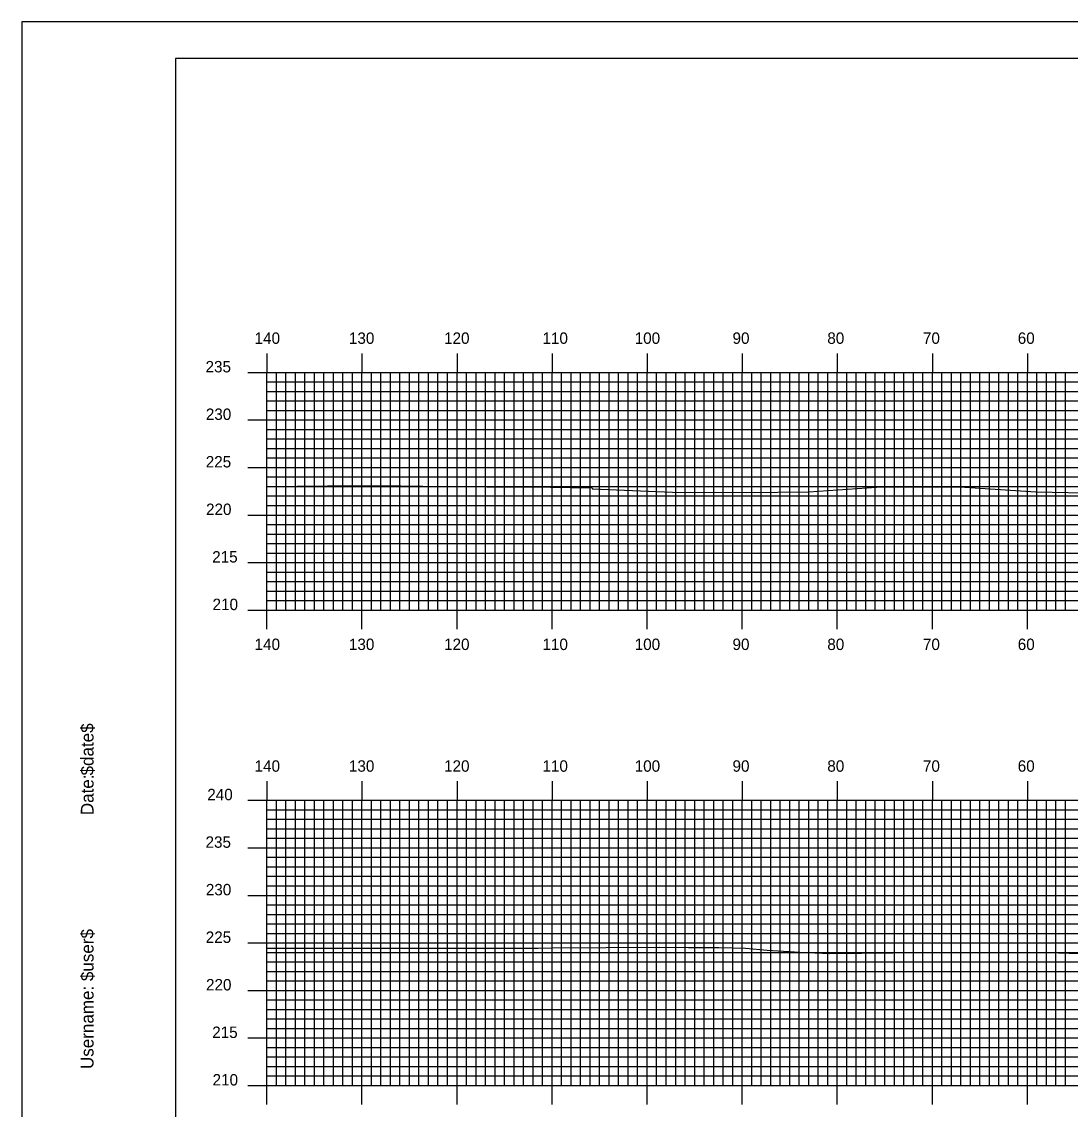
# Model space of a CAD drawing. Extents: x 1803897 to 1804240, y 442591 to 442811.
# Drawn here: x 1803896.9 to 1804007.2, y 442696.2 to 442810.5 of the extents above; entities that cross this region are included whole.
import ezdxf

# ---------------------------------------------------------------- set-up
doc = ezdxf.new("R2010")
doc.units = 0
for name, color, linetype in [('BORDER', 7, 'Continuous'), ('H_V ANNOTATION', 7, 'Continuous'), ('MAJOR', 7, 'Continuous'), ('MINOR', 7, 'Continuous'), ('PLOT BOUNDARY', 7, 'Continuous'), ('S_Roadway_Centerline', 7, 'Continuous')]:
    doc.layers.add(name, color=color, linetype=linetype)

msp = doc.modelspace()

# ---------------------------------------------------------------- linework, layer by layer
at = {"layer": 'BORDER'}
msp.add_lwpolyline([(1803913.05, 442596.67), (1804233.05, 442596.67), (1804233.05, 442806.67), (1803913.05, 442806.67)], close=True, dxfattribs=at)
at = {"layer": 'MAJOR'}
for p, q in [((1803922.65, 442775.67), (1803922.65, 442773.67)), ((1803932.65, 442775.67), (1803932.65, 442773.67)), ((1803942.65, 442775.67), (1803942.65, 442773.67)), ((1803952.65, 442775.67), (1803952.65, 442773.67)), ((1803962.65, 442775.67), (1803962.65, 442773.67)), ((1803972.65, 442775.67), (1803972.65, 442773.67)), ((1803982.65, 442775.67), (1803982.65, 442773.67)), ((1803992.65, 442775.67), (1803992.65, 442773.67)), ((1804002.65, 442775.67), (1804002.65, 442773.67)), ((1803920.65, 442773.67), (1803922.65, 442773.67)), ((1803922.65, 442773.67), (1804202.65, 442773.67)), ((1803922.65, 442748.67), (1803922.65, 442773.67)), ((1803922.65, 442748.67), (1803922.65, 442773.67)), ((1803922.65, 442773.67), (1804202.65, 442773.67)), ((1803932.65, 442748.67), (1803932.65, 442773.67)), ((1803942.65, 442748.67), (1803942.65, 442773.67)), ((1803952.65, 442748.67), (1803952.65, 442773.67)), ((1803962.65, 442748.67), (1803962.65, 442773.67)), ((1803972.65, 442748.67), (1803972.65, 442773.67)), ((1803982.65, 442748.67), (1803982.65, 442773.67)), ((1803992.65, 442748.67), (1803992.65, 442773.67)), ((1804002.65, 442748.67), (1804002.65, 442773.67)), ((1803920.65, 442768.67), (1803922.65, 442768.67)), ((1803922.65, 442768.67), (1804202.65, 442768.67)), ((1803920.65, 442763.67), (1803922.65, 442763.67)), ((1803922.65, 442763.67), (1804202.65, 442763.67)), ((1803920.65, 442758.67), (1803922.65, 442758.67)), ((1803922.65, 442758.67), (1804202.65, 442758.67)), ((1803920.65, 442753.67), (1803922.65, 442753.67)), ((1803922.65, 442753.67), (1804202.65, 442753.67)), ((1803920.65, 442748.67), (1803922.65, 442748.67)), ((1803922.65, 442748.67), (1804202.65, 442748.67)), ((1803922.65, 442748.67), (1804202.65, 442748.67)), ((1803922.65, 442746.66), (1803922.65, 442748.67)), ((1803932.65, 442746.66), (1803932.65, 442748.67)), ((1803942.65, 442746.66), (1803942.65, 442748.67)), ((1803952.65, 442746.66), (1803952.65, 442748.67)), ((1803962.65, 442746.66), (1803962.65, 442748.67)), ((1803972.65, 442746.66), (1803972.65, 442748.67)), ((1803982.65, 442746.66), (1803982.65, 442748.67)), ((1803992.65, 442746.66), (1803992.65, 442748.67)), ((1804002.65, 442746.66), (1804002.65, 442748.67)), ((1803922.65, 442730.67), (1803922.65, 442728.67)), ((1803932.65, 442730.67), (1803932.65, 442728.67)), ((1803942.65, 442730.67), (1803942.65, 442728.67)), ((1803952.65, 442730.67), (1803952.65, 442728.67)), ((1803962.65, 442730.67), (1803962.65, 442728.67)), ((1803972.65, 442730.67), (1803972.65, 442728.67)), ((1803982.65, 442730.67), (1803982.65, 442728.67)), ((1803992.65, 442730.67), (1803992.65, 442728.67)), ((1804002.65, 442730.67), (1804002.65, 442728.67)), ((1803920.65, 442728.67), (1803922.65, 442728.67)), ((1803922.65, 442728.67), (1804202.65, 442728.67)), ((1803922.65, 442698.67), (1803922.65, 442728.67)), ((1803922.65, 442698.67), (1803922.65, 442728.67)), ((1803922.65, 442728.67), (1804202.65, 442728.67)), ((1803932.65, 442698.67), (1803932.65, 442728.67)), ((1803942.65, 442698.67), (1803942.65, 442728.67)), ((1803952.65, 442698.67), (1803952.65, 442728.67)), ((1803962.65, 442698.67), (1803962.65, 442728.67)), ((1803972.65, 442698.67), (1803972.65, 442728.67)), ((1803982.65, 442698.67), (1803982.65, 442728.67)), ((1803992.65, 442698.67), (1803992.65, 442728.67)), ((1804002.65, 442698.67), (1804002.65, 442728.67)), ((1803920.65, 442723.67), (1803922.65, 442723.67)), ((1803922.65, 442723.67), (1804202.65, 442723.67)), ((1803920.65, 442718.67), (1803922.65, 442718.67)), ((1803922.65, 442718.67), (1804202.65, 442718.67)), ((1803920.65, 442713.67), (1803922.65, 442713.67)), ((1803922.65, 442713.67), (1804202.65, 442713.67)), ((1803920.65, 442708.67), (1803922.65, 442708.67)), ((1803922.65, 442708.67), (1804202.65, 442708.67)), ((1803920.65, 442703.67), (1803922.65, 442703.67)), ((1803922.65, 442703.67), (1804202.65, 442703.67)), ((1803920.65, 442698.67), (1803922.65, 442698.67)), ((1803922.65, 442698.67), (1804202.65, 442698.67)), ((1803922.65, 442698.67), (1804202.65, 442698.67)), ((1803922.65, 442696.66), (1803922.65, 442698.67)), ((1803932.65, 442696.66), (1803932.65, 442698.67)), ((1803942.65, 442696.66), (1803942.65, 442698.67)), ((1803952.65, 442696.66), (1803952.65, 442698.67)), ((1803962.65, 442696.66), (1803962.65, 442698.67)), ((1803972.65, 442696.66), (1803972.65, 442698.67)), ((1803982.65, 442696.66), (1803982.65, 442698.67)), ((1803992.65, 442696.66), (1803992.65, 442698.67)), ((1804002.65, 442696.66), (1804002.65, 442698.67))]:
    msp.add_line(p, q, dxfattribs=at)
at = {"layer": 'MINOR'}
for p, q in [((1803923.65, 442748.67), (1803923.65, 442773.67)), ((1803924.65, 442748.67), (1803924.65, 442773.67)), ((1803925.65, 442748.67), (1803925.65, 442773.67)), ((1803926.65, 442748.67), (1803926.65, 442773.67)), ((1803927.65, 442748.67), (1803927.65, 442773.67)), ((1803928.65, 442748.67), (1803928.65, 442773.67)), ((1803929.65, 442748.67), (1803929.65, 442773.67)), ((1803930.65, 442748.67), (1803930.65, 442773.67)), ((1803931.65, 442748.67), (1803931.65, 442773.67)), ((1803933.65, 442748.67), (1803933.65, 442773.67)), ((1803934.65, 442748.67), (1803934.65, 442773.67)), ((1803935.65, 442748.67), (1803935.65, 442773.67)), ((1803936.65, 442748.67), (1803936.65, 442773.67)), ((1803937.65, 442748.67), (1803937.65, 442773.67)), ((1803938.65, 442748.67), (1803938.65, 442773.67)), ((1803939.65, 442748.67), (1803939.65, 442773.67)), ((1803940.65, 442748.67), (1803940.65, 442773.67)), ((1803941.65, 442748.67), (1803941.65, 442773.67)), ((1803943.65, 442748.67), (1803943.65, 442773.67)), ((1803944.65, 442748.67), (1803944.65, 442773.67)), ((1803945.65, 442748.67), (1803945.65, 442773.67)), ((1803946.65, 442748.67), (1803946.65, 442773.67)), ((1803947.65, 442748.67), (1803947.65, 442773.67)), ((1803948.65, 442748.67), (1803948.65, 442773.67)), ((1803949.65, 442748.67), (1803949.65, 442773.67)), ((1803950.65, 442748.67), (1803950.65, 442773.67)), ((1803951.65, 442748.67), (1803951.65, 442773.67)), ((1803953.65, 442748.67), (1803953.65, 442773.67)), ((1803954.65, 442748.67), (1803954.65, 442773.67)), ((1803955.65, 442748.67), (1803955.65, 442773.67)), ((1803956.65, 442748.67), (1803956.65, 442773.67)), ((1803957.65, 442748.67), (1803957.65, 442773.67)), ((1803958.65, 442748.67), (1803958.65, 442773.67)), ((1803959.65, 442748.67), (1803959.65, 442773.67)), ((1803960.65, 442748.67), (1803960.65, 442773.67)), ((1803961.65, 442748.67), (1803961.65, 442773.67)), ((1803963.65, 442748.67), (1803963.65, 442773.67)), ((1803964.65, 442748.67), (1803964.65, 442773.67)), ((1803965.65, 442748.67), (1803965.65, 442773.67)), ((1803966.65, 442748.67), (1803966.65, 442773.67)), ((1803967.65, 442748.67), (1803967.65, 442773.67)), ((1803968.65, 442748.67), (1803968.65, 442773.67)), ((1803969.65, 442748.67), (1803969.65, 442773.67)), ((1803970.65, 442748.67), (1803970.65, 442773.67)), ((1803971.65, 442748.67), (1803971.65, 442773.67)), ((1803973.65, 442748.67), (1803973.65, 442773.67)), ((1803974.65, 442748.67), (1803974.65, 442773.67)), ((1803975.65, 442748.67), (1803975.65, 442773.67)), ((1803976.65, 442748.67), (1803976.65, 442773.67)), ((1803977.65, 442748.67), (1803977.65, 442773.67)), ((1803978.65, 442748.67), (1803978.65, 442773.67)), ((1803979.65, 442748.67), (1803979.65, 442773.67)), ((1803980.65, 442748.67), (1803980.65, 442773.67)), ((1803981.65, 442748.67), (1803981.65, 442773.67)), ((1803983.65, 442748.67), (1803983.65, 442773.67)), ((1803984.65, 442748.67), (1803984.65, 442773.67)), ((1803985.65, 442748.67), (1803985.65, 442773.67)), ((1803986.65, 442748.67), (1803986.65, 442773.67)), ((1803987.65, 442748.67), (1803987.65, 442773.67)), ((1803988.65, 442748.67), (1803988.65, 442773.67)), ((1803989.65, 442748.67), (1803989.65, 442773.67)), ((1803990.65, 442748.67), (1803990.65, 442773.67)), ((1803991.65, 442748.67), (1803991.65, 442773.67)), ((1803993.65, 442748.67), (1803993.65, 442773.67)), ((1803994.65, 442748.67), (1803994.65, 442773.67)), ((1803995.65, 442748.67), (1803995.65, 442773.67)), ((1803996.65, 442748.67), (1803996.65, 442773.67)), ((1803997.65, 442748.67), (1803997.65, 442773.67)), ((1803998.65, 442748.67), (1803998.65, 442773.67)), ((1803999.65, 442748.67), (1803999.65, 442773.67)), ((1804000.65, 442748.67), (1804000.65, 442773.67)), ((1804001.65, 442748.67), (1804001.65, 442773.67)), ((1804003.65, 442748.67), (1804003.65, 442773.67)), ((1804004.65, 442748.67), (1804004.65, 442773.67)), ((1804005.65, 442748.67), (1804005.65, 442773.67)), ((1804006.65, 442748.67), (1804006.65, 442773.67)), ((1803922.65, 442772.67), (1804202.65, 442772.67)), ((1803922.65, 442772.67), (1803924.66, 442772.67)), ((1803922.65, 442771.67), (1804202.65, 442771.67)), ((1803922.65, 442771.67), (1803924.66, 442771.67)), ((1803922.65, 442770.67), (1804202.65, 442770.67)), ((1803922.65, 442770.67), (1803924.66, 442770.67)), ((1803922.65, 442769.67), (1804202.65, 442769.67)), ((1803922.65, 442769.67), (1803924.66, 442769.67)), ((1803922.65, 442767.67), (1804202.65, 442767.67)), ((1803922.65, 442767.67), (1803924.66, 442767.67)), ((1803922.65, 442766.67), (1804202.65, 442766.67)), ((1803922.65, 442766.67), (1803924.66, 442766.67)), ((1803922.65, 442765.67), (1804202.65, 442765.67)), ((1803922.65, 442765.67), (1803924.66, 442765.67)), ((1803922.65, 442764.67), (1804202.65, 442764.67)), ((1803922.65, 442764.67), (1803924.66, 442764.67)), ((1803922.65, 442762.67), (1804202.65, 442762.67)), ((1803922.65, 442762.67), (1803924.66, 442762.67)), ((1803922.65, 442761.67), (1804202.65, 442761.67)), ((1803922.65, 442761.67), (1803924.66, 442761.67)), ((1803922.65, 442760.67), (1804202.65, 442760.67)), ((1803922.65, 442760.67), (1803924.66, 442760.67)), ((1803922.65, 442759.67), (1804202.65, 442759.67)), ((1803922.65, 442759.67), (1803924.66, 442759.67)), ((1803922.65, 442757.67), (1804202.65, 442757.67)), ((1803922.65, 442757.67), (1803924.66, 442757.67)), ((1803922.65, 442756.67), (1804202.65, 442756.67)), ((1803922.65, 442756.67), (1803924.66, 442756.67)), ((1803922.65, 442755.67), (1804202.65, 442755.67)), ((1803922.65, 442755.67), (1803924.66, 442755.67)), ((1803922.65, 442754.67), (1804202.65, 442754.67)), ((1803922.65, 442754.67), (1803924.66, 442754.67)), ((1803922.65, 442752.67), (1804202.65, 442752.67)), ((1803922.65, 442752.67), (1803924.66, 442752.67)), ((1803922.65, 442751.67), (1804202.65, 442751.67)), ((1803922.65, 442751.67), (1803924.66, 442751.67)), ((1803922.65, 442750.67), (1804202.65, 442750.67)), ((1803922.65, 442750.67), (1803924.66, 442750.67)), ((1803922.65, 442749.67), (1804202.65, 442749.67)), ((1803922.65, 442749.67), (1803924.66, 442749.67)), ((1803922.65, 442727.67), (1804202.65, 442727.67)), ((1803922.65, 442727.67), (1803924.66, 442727.67)), ((1803923.65, 442698.67), (1803923.65, 442728.67)), ((1803924.65, 442698.67), (1803924.65, 442728.67)), ((1803925.65, 442698.67), (1803925.65, 442728.67)), ((1803926.65, 442698.67), (1803926.65, 442728.67)), ((1803927.65, 442698.67), (1803927.65, 442728.67)), ((1803928.65, 442698.67), (1803928.65, 442728.67)), ((1803929.65, 442698.67), (1803929.65, 442728.67)), ((1803930.65, 442698.67), (1803930.65, 442728.67)), ((1803931.65, 442698.67), (1803931.65, 442728.67)), ((1803933.65, 442698.67), (1803933.65, 442728.67)), ((1803934.65, 442698.67), (1803934.65, 442728.67)), ((1803935.65, 442698.67), (1803935.65, 442728.67)), ((1803936.65, 442698.67), (1803936.65, 442728.67)), ((1803937.65, 442698.67), (1803937.65, 442728.67)), ((1803938.65, 442698.67), (1803938.65, 442728.67)), ((1803939.65, 442698.67), (1803939.65, 442728.67)), ((1803940.65, 442698.67), (1803940.65, 442728.67)), ((1803941.65, 442698.67), (1803941.65, 442728.67)), ((1803943.65, 442698.67), (1803943.65, 442728.67)), ((1803944.65, 442698.67), (1803944.65, 442728.67)), ((1803945.65, 442698.67), (1803945.65, 442728.67)), ((1803946.65, 442698.67), (1803946.65, 442728.67)), ((1803947.65, 442698.67), (1803947.65, 442728.67)), ((1803948.65, 442698.67), (1803948.65, 442728.67)), ((1803949.65, 442698.67), (1803949.65, 442728.67)), ((1803950.65, 442698.67), (1803950.65, 442728.67)), ((1803951.65, 442698.67), (1803951.65, 442728.67)), ((1803953.65, 442698.67), (1803953.65, 442728.67)), ((1803954.65, 442698.67), (1803954.65, 442728.67)), ((1803955.65, 442698.67), (1803955.65, 442728.67)), ((1803956.65, 442698.67), (1803956.65, 442728.67)), ((1803957.65, 442698.67), (1803957.65, 442728.67)), ((1803958.65, 442698.67), (1803958.65, 442728.67)), ((1803959.65, 442698.67), (1803959.65, 442728.67)), ((1803960.65, 442698.67), (1803960.65, 442728.67)), ((1803961.65, 442698.67), (1803961.65, 442728.67)), ((1803963.65, 442698.67), (1803963.65, 442728.67)), ((1803964.65, 442698.67), (1803964.65, 442728.67)), ((1803965.65, 442698.67), (1803965.65, 442728.67)), ((1803966.65, 442698.67), (1803966.65, 442728.67)), ((1803967.65, 442698.67), (1803967.65, 442728.67)), ((1803968.65, 442698.67), (1803968.65, 442728.67)), ((1803969.65, 442698.67), (1803969.65, 442728.67)), ((1803970.65, 442698.67), (1803970.65, 442728.67)), ((1803971.65, 442698.67), (1803971.65, 442728.67)), ((1803973.65, 442698.67), (1803973.65, 442728.67)), ((1803974.65, 442698.67), (1803974.65, 442728.67)), ((1803975.65, 442698.67), (1803975.65, 442728.67)), ((1803976.65, 442698.67), (1803976.65, 442728.67)), ((1803977.65, 442698.67), (1803977.65, 442728.67)), ((1803978.65, 442698.67), (1803978.65, 442728.67)), ((1803979.65, 442698.67), (1803979.65, 442728.67)), ((1803980.65, 442698.67), (1803980.65, 442728.67)), ((1803981.65, 442698.67), (1803981.65, 442728.67)), ((1803983.65, 442698.67), (1803983.65, 442728.67)), ((1803984.65, 442698.67), (1803984.65, 442728.67)), ((1803985.65, 442698.67), (1803985.65, 442728.67)), ((1803986.65, 442698.67), (1803986.65, 442728.67)), ((1803987.65, 442698.67), (1803987.65, 442728.67)), ((1803988.65, 442698.67), (1803988.65, 442728.67)), ((1803989.65, 442698.67), (1803989.65, 442728.67)), ((1803990.65, 442698.67), (1803990.65, 442728.67)), ((1803991.65, 442698.67), (1803991.65, 442728.67)), ((1803993.65, 442698.67), (1803993.65, 442728.67)), ((1803994.65, 442698.67), (1803994.65, 442728.67)), ((1803995.65, 442698.67), (1803995.65, 442728.67)), ((1803996.65, 442698.67), (1803996.65, 442728.67)), ((1803997.65, 442698.67), (1803997.65, 442728.67)), ((1803998.65, 442698.67), (1803998.65, 442728.67)), ((1803999.65, 442698.67), (1803999.65, 442728.67)), ((1804000.65, 442698.67), (1804000.65, 442728.67)), ((1804001.65, 442698.67), (1804001.65, 442728.67)), ((1804003.65, 442698.67), (1804003.65, 442728.67)), ((1804004.65, 442698.67), (1804004.65, 442728.67)), ((1804005.65, 442698.67), (1804005.65, 442728.67)), ((1804006.65, 442698.67), (1804006.65, 442728.67)), ((1803922.65, 442726.67), (1804202.65, 442726.67)), ((1803922.65, 442726.67), (1803924.66, 442726.67)), ((1803922.65, 442725.67), (1804202.65, 442725.67)), ((1803922.65, 442725.67), (1803924.66, 442725.67)), ((1803922.65, 442724.67), (1804202.65, 442724.67)), ((1803922.65, 442724.67), (1803924.66, 442724.67)), ((1803922.65, 442722.67), (1804202.65, 442722.67)), ((1803922.65, 442722.67), (1803924.66, 442722.67)), ((1803922.65, 442721.67), (1804202.65, 442721.67)), ((1803922.65, 442721.67), (1803924.66, 442721.67)), ((1803922.65, 442720.67), (1804202.65, 442720.67)), ((1803922.65, 442720.67), (1803924.66, 442720.67)), ((1803922.65, 442719.67), (1804202.65, 442719.67)), ((1803922.65, 442719.67), (1803924.66, 442719.67)), ((1803922.65, 442717.67), (1804202.65, 442717.67)), ((1803922.65, 442717.67), (1803924.66, 442717.67)), ((1803922.65, 442716.67), (1804202.65, 442716.67)), ((1803922.65, 442716.67), (1803924.66, 442716.67)), ((1803922.65, 442715.67), (1804202.65, 442715.67)), ((1803922.65, 442715.67), (1803924.66, 442715.67)), ((1803922.65, 442714.67), (1804202.65, 442714.67)), ((1803922.65, 442714.67), (1803924.66, 442714.67)), ((1803922.65, 442712.67), (1804202.65, 442712.67)), ((1803922.65, 442712.67), (1803924.66, 442712.67)), ((1803922.65, 442711.67), (1804202.65, 442711.67)), ((1803922.65, 442711.67), (1803924.66, 442711.67)), ((1803922.65, 442710.67), (1804202.65, 442710.67)), ((1803922.65, 442710.67), (1803924.66, 442710.67)), ((1803922.65, 442709.67), (1804202.65, 442709.67)), ((1803922.65, 442709.67), (1803924.66, 442709.67)), ((1803922.65, 442707.67), (1804202.65, 442707.67)), ((1803922.65, 442707.67), (1803924.66, 442707.67)), ((1803922.65, 442706.67), (1804202.65, 442706.67)), ((1803922.65, 442706.67), (1803924.66, 442706.67)), ((1803922.65, 442705.67), (1804202.65, 442705.67)), ((1803922.65, 442705.67), (1803924.66, 442705.67)), ((1803922.65, 442704.67), (1804202.65, 442704.67)), ((1803922.65, 442704.67), (1803924.66, 442704.67)), ((1803922.65, 442702.67), (1804202.65, 442702.67)), ((1803922.65, 442702.67), (1803924.66, 442702.67)), ((1803922.65, 442701.67), (1804202.65, 442701.67)), ((1803922.65, 442701.67), (1803924.66, 442701.67)), ((1803922.65, 442700.67), (1804202.65, 442700.67)), ((1803922.65, 442700.67), (1803924.66, 442700.67)), ((1803922.65, 442699.67), (1804202.65, 442699.67)), ((1803922.65, 442699.67), (1803924.66, 442699.67))]:
    msp.add_line(p, q, dxfattribs=at)
at = {"layer": 'PLOT BOUNDARY'}
msp.add_lwpolyline([(1803896.87, 442590.55), (1804236.87, 442590.55), (1804236.87, 442810.55), (1803896.87, 442810.55)], close=True, dxfattribs=at)
at = {"layer": 'S_Roadway_Centerline'}
for points in [[(1803922.65, 442761.66), (1803929.02, 442761.73), (1803932.85, 442761.75), (1803936.73, 442761.74), (1803943.66, 442761.62), (1803945.05, 442761.66), (1803945.78, 442761.65), (1803952.5, 442761.61), (1803956.85, 442761.53), (1803956.89, 442761.42), (1803965.3, 442761.06), (1803973.09, 442761.04), (1803979.65, 442761.1), (1803986.77, 442761.6), (1803995.53, 442761.64), (1804003.55, 442761.09), (1804010.38, 442760.96)], [(1803922.65, 442713.13), (1803929.44, 442713.13), (1803941.59, 442713.12), (1803951.2, 442713.11), (1803952.68, 442713.16), (1803963.95, 442713.21), (1803966.99, 442713.19), (1803970.2, 442713.19), (1803972.99, 442713.1), (1803975.27, 442712.91), (1803978.72, 442712.69), (1803981.87, 442712.56), (1803995.17, 442712.71), (1804004.8, 442712.66), (1804017.13, 442712.26)]]:
    msp.add_lwpolyline(points, dxfattribs=at)

# ---------------------------------------------------------------- texts
at = {"layer": 'BORDER'}
for s, p in [('$date$', (1803904.42, 442731.28)), ('Date:', (1803904.42, 442727.1)), ('$user$', (1803904.42, 442709.65)), ('Username:', (1803904.42, 442700.4))]:
    msp.add_text(s, height=1.339, rotation=90, dxfattribs=at).set_placement(p)
at = {"layer": 'H_V ANNOTATION'}
for s, p in [('140', (1803921.36, 442776.67)), ('130', (1803931.28, 442776.67)), ('120', (1803941.29, 442776.67)), ('110', (1803951.64, 442776.67)), ('100', (1803961.34, 442776.67)), ('90', (1803971.63, 442776.67)), ('80', (1803981.6, 442776.67)), ('70', (1803991.66, 442776.67)), ('60', (1804001.63, 442776.67)), ('235', (1803916.2, 442773.67)), ('230', (1803916.23, 442768.67)), ('225', (1803916.22, 442763.67)), ('220', (1803916.25, 442758.67)), ('215', (1803916.9, 442753.67)), ('210', (1803916.94, 442748.67)), ('140', (1803921.36, 442744.47)), ('130', (1803931.28, 442744.47)), ('120', (1803941.29, 442744.47)), ('110', (1803951.64, 442744.47)), ('100', (1803961.34, 442744.47)), ('90', (1803971.63, 442744.47)), ('80', (1803981.6, 442744.47)), ('70', (1803991.66, 442744.47)), ('60', (1804001.63, 442744.47)), ('140', (1803921.36, 442731.67)), ('130', (1803931.28, 442731.67)), ('120', (1803941.29, 442731.67)), ('110', (1803951.64, 442731.67)), ('100', (1803961.34, 442731.67)), ('90', (1803971.63, 442731.67)), ('80', (1803981.6, 442731.67)), ('70', (1803991.66, 442731.67)), ('60', (1804001.63, 442731.67)), ('240', (1803916.38, 442728.67)), ('235', (1803916.2, 442723.67)), ('230', (1803916.23, 442718.67)), ('225', (1803916.22, 442713.67)), ('220', (1803916.25, 442708.67)), ('215', (1803916.9, 442703.67)), ('210', (1803916.94, 442698.67))]:
    msp.add_text(s, height=1.2, dxfattribs=at).set_placement(p)
at = {"layer": 'MAJOR'}
for p in [(1803922.65, 442748.67), (1803922.65, 442698.67)]:
    msp.add_text('-', height=0.012, dxfattribs=at).set_placement(p)

doc.saveas('drawing.dxf')
